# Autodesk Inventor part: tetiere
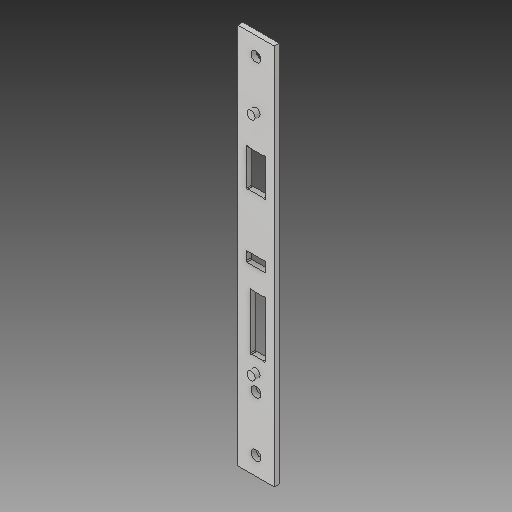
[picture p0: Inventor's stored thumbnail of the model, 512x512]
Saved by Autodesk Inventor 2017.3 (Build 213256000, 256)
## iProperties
Created: 2007-12
Part Number: tetiere
Material: Générique
Document SubType Name: Modeling
Designer: ficho
Density: 1 g/cm^3
Appearance: Par défaut
Author: ficho
Sending System: SolidWorks 2009
Last Author: christophe
Last Saved: 2011-02-10
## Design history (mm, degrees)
extrude "Extrusion2"
node "Solide1"
